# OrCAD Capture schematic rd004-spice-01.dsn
size A
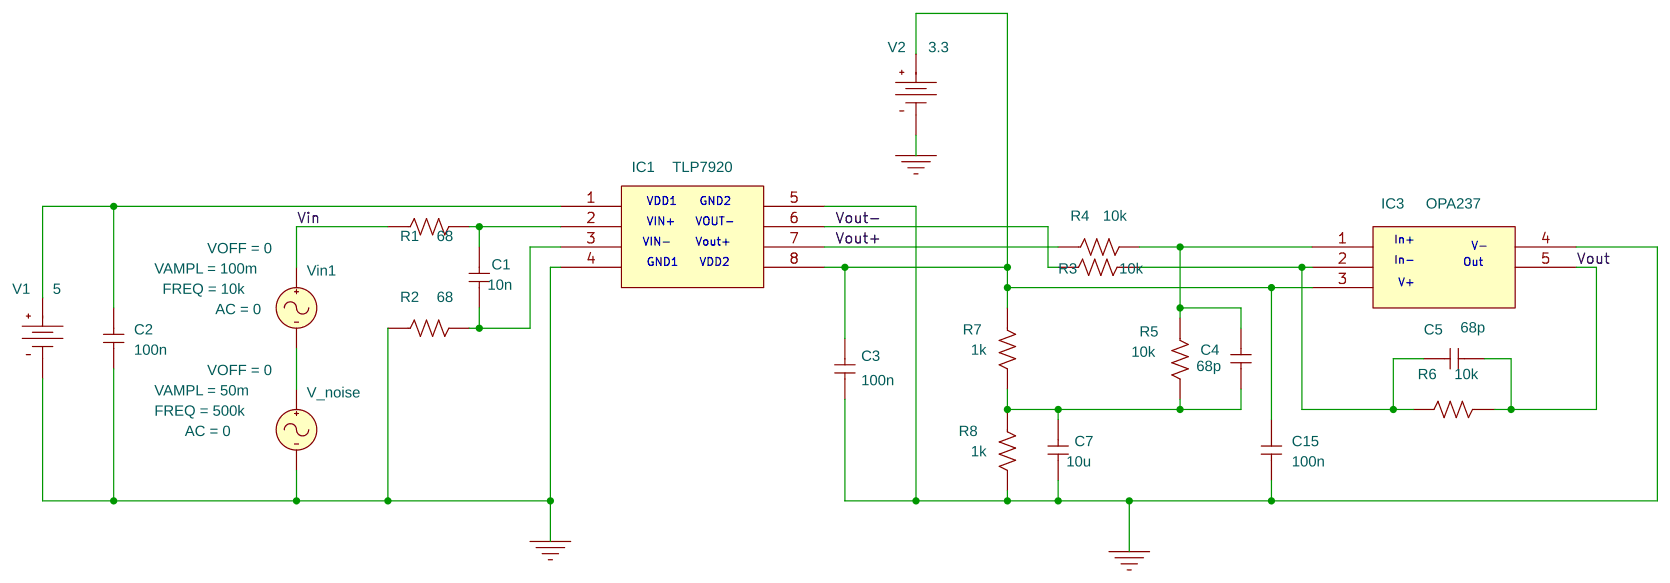
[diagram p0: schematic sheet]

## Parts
C1  10n  [RAD/CK05]
C2  100n  [RAD/CK05]
C3  100n  [RAD/CK05]
C4  68p  [RAD/CK05]
C5  68p  [RAD/CK05]
C7  10u  [RAD/CK05]
C15  100n  [RAD/CK05]
IC1  TLP7920
IC3  OPA237
R1  68  [AX/RC05]
R2  68  [AX/RC05]
R3  10k  [AX/RC05]
R4  10k  [AX/RC05]
R5  10k  [AX/RC05]
R6  10k  [AX/RC05]
R7  1k  [AX/RC05]
R8  1k  [AX/RC05]
V1  VDC
V2  VDC
V_noise  VSIN
Vin1  VSIN

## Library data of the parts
C1-C5 C7 C15 = C
IC1 = TLP7920
IC3 = OPA237
R1-R8 = R
V1 = VDC: DC: 5
V2 = VDC: DC: 3.3
V_noise = VSIN: AC: 0; FREQ: 500k; VAMPL: 50m; VOFF: 0
Vin1 = VSIN: AC: 0; FREQ: 10k; VAMPL: 100m; VOFF: 0

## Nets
Vin: R1.1 Vin1.1(+)
0: C2.1 C3.1 C7.1 C15.1 IC1.4 IC1.5 IC3.4 R2.1 R8.2 V1.1(-) V2.1(-) V_noise.2(-)
Vout: C5.1 IC3.5 R6.1
Vout+: IC1.7 R4.1
Vout-: IC1.6 R3.2
N131203: C3.2 C15.2 IC1.8 IC3.3 R7.1 V2.0(+)
N131293: C2.2 IC1.1 V1.0(+)
N131355: C1.1 IC1.2 R1.2
N131435: C1.2 IC1.3 R2.2
N131477: C4.1 IC3.1 R4.2 R5.1
N131549: C5.2 IC3.2 R3.1 R6.2
N131773: V_noise.1(+) Vin1.2(-)
N131839: C4.2 C7.2 R5.2 R7.2 R8.1

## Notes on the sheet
- VDD1
- GND2
- VIN+
- VOUT-
- VIN-
- Vout+
- In+
- In-
- V-
- GND1
- VDD2
- V+
- Out
